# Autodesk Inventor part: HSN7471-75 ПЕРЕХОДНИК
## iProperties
Created: 2011-02
Part Number: HSN7471-75 ПЕРЕХОДНИК
Document SubType Name: Modeling
Designer: Чернышев Юрий
Mass: 8136.46 g
Surface Area: 3365.01 cm^2
Volume: 8136.46 cm^3
Density: 1 g/cm^3
Author: Чернышев Юрий
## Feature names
1. ExtrusionBlind1
2. ExtrusionBlind2
3. ExtrusionBlind3
4. ExtrusionBlind4
5. Fillet8
6. ExtrusionBlind5
7. ExtrusionToPlane1
8. ExtrusionToPlane2
9. ExtrusionToPlane3
10. SweepToPlane1
11. RevolutionAngle1
12. Fillet9
13. Fillet10
14. Hole1
15. Hole2
16. Hole3
17. Hole4
18. Hole5
19. Hole6
20. Hole7
21. Hole8
22. Hole9
23. Hole10
24. Hole11
25. Hole12
26. Fillet11
27. Fillet12
28. Fillet13
29. Fillet14
30. Fillet20
31. Fillet21
32. Fillet22
33. ExtrusionBlind6
34. Hole13
35. RectangularPattern1
36. Fillet23
37. Fillet24
38. Fillet25
39. Fillet26
40. Fillet27
41. Fillet28
42. Fillet29
43. Fillet30
44. Fillet31
45. Fillet32
46. Fillet33
47. Fillet34
48. Fillet35
49. Hole14
